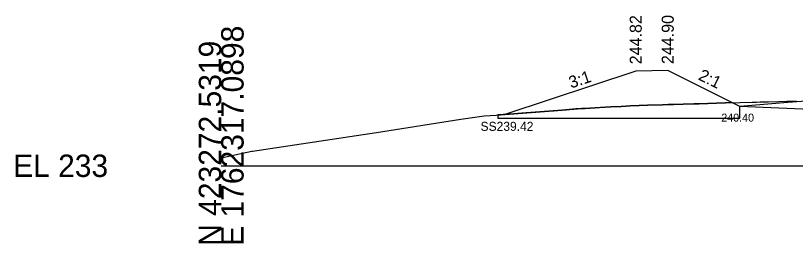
# Model space of a CAD drawing. Extents: x -26 to 3203, y -11010 to 4024.
# Drawn here: x -25.7 to 71.8, y 1490.3 to 1518.7 of the extents above; entities that cross this region are included whole.
import ezdxf

# ---------------------------------------------------------------- set-up
doc = ezdxf.new("R2010")
doc.units = 0
for name, color, linetype in [('Default', 7, 'Continuous'), ('Exist Cross Section Cell', 7, 'Continuous'), ('Exist XS Ground Line', 7, 'Continuous'), ('Prop CMT Slope Grass', 7, 'Continuous'), ('Prop CMT Subgrade Earthwork', 7, 'Continuous'), ('Prop CMT Undercut', 7, 'Continuous'), ('Prop CMT Undercut Boundary', 7, 'Continuous'), ('Prop XS Hydro Elevations', 7, 'Continuous'), ('Prop XS Side Slope Text', 7, 'Continuous'), ('Prop XS SS Elevation Text', 7, 'Continuous'), ('Scratch_Level_0', 7, 'Continuous')]:
    doc.layers.add(name, color=color, linetype=linetype)

msp = doc.modelspace()

# ---------------------------------------------------------------- linework, layer by layer
at = {"layer": 'Exist Cross Section Cell'}
msp.add_line((0, 1500), (100, 1500), dxfattribs=at)
at = {"layer": 'Exist XS Ground Line'}
msp.add_lwpolyline([(0, 1501.007), (3.245, 1501.693), (3.814, 1501.81), (3.917, 1501.827), (16.92, 1503.777), (19.387, 1504.149), (29.925, 1505.822), (32.864, 1506.212), (32.872, 1506.25), (34.364, 1506.327), (42.596, 1506.947), (45.013, 1507.156), (45.295, 1507.16), (45.468, 1507.167), (46.715, 1507.236), (47.263, 1507.263), (48.709, 1507.339), (49.975, 1507.402), (50.616, 1507.436), (51.09, 1507.463), (52.218, 1507.52), (52.239, 1507.521), (53.251, 1507.56), (55.147, 1507.621), (55.839, 1507.64), (56.531, 1507.661), (57.745, 1507.697), (59.064, 1507.73), (59.416, 1507.74), (59.737, 1507.749), (62.971, 1507.844), (62.989, 1507.845), (63.005, 1507.845), (64.862, 1507.892), (66.348, 1507.938), (66.597, 1507.945), (66.902, 1507.953), (67.349, 1507.97), (67.464, 1507.974), (67.569, 1507.978), (67.628, 1507.98), (68.359, 1507.998), (69.673, 1508.031), (70.697, 1508.055), (71.89, 1508.081)], dxfattribs=at)
msp.add_lwpolyline([(0, 1501.007), (3.245, 1501.693), (3.814, 1501.81), (3.917, 1501.827), (16.92, 1503.777), (19.387, 1504.149), (29.925, 1505.822), (32.864, 1506.212), (32.872, 1506.25), (34.364, 1506.327), (42.596, 1506.947), (45.013, 1507.156), (45.295, 1507.16), (45.468, 1507.167), (46.715, 1507.236), (47.263, 1507.263), (48.709, 1507.339), (49.975, 1507.402), (50.616, 1507.436), (51.09, 1507.463), (52.218, 1507.52), (52.239, 1507.521), (53.251, 1507.56), (55.147, 1507.621), (55.839, 1507.64), (56.531, 1507.661), (57.745, 1507.697), (59.064, 1507.73), (59.416, 1507.74), (59.737, 1507.749), (62.971, 1507.844), (62.989, 1507.845), (63.005, 1507.845), (64.862, 1507.892), (66.348, 1507.938), (66.597, 1507.945), (66.902, 1507.953), (67.349, 1507.97), (67.464, 1507.974), (67.569, 1507.978), (67.628, 1507.98), (68.359, 1507.998), (69.673, 1508.031), (70.697, 1508.055), (71.89, 1508.081)], dxfattribs=at)
msp.add_lwpolyline([(0, 1501.007), (3.245, 1501.693), (3.814, 1501.81), (3.917, 1501.827), (16.92, 1503.777), (19.387, 1504.149), (29.925, 1505.822), (32.864, 1506.212), (32.872, 1506.25), (34.364, 1506.327), (42.596, 1506.947), (45.013, 1507.156), (45.295, 1507.16), (45.468, 1507.167), (46.715, 1507.236), (47.263, 1507.263), (48.709, 1507.339), (49.975, 1507.402), (50.616, 1507.436), (51.09, 1507.463), (52.218, 1507.52), (52.239, 1507.521), (53.251, 1507.56), (55.147, 1507.621), (55.839, 1507.64), (56.531, 1507.661), (57.745, 1507.697), (59.064, 1507.73), (59.416, 1507.74), (59.737, 1507.749), (62.971, 1507.844), (62.989, 1507.845), (63.005, 1507.845), (64.862, 1507.892), (66.348, 1507.938), (66.597, 1507.945), (66.902, 1507.953), (67.349, 1507.97), (67.464, 1507.974), (67.569, 1507.978), (67.628, 1507.98), (68.359, 1507.998), (69.673, 1508.031), (70.697, 1508.055), (71.89, 1508.081)], dxfattribs=at)
msp.add_lwpolyline([(0, 1501.007), (3.245, 1501.693), (3.814, 1501.81), (3.917, 1501.827), (16.92, 1503.777), (19.387, 1504.149), (29.925, 1505.822), (32.864, 1506.212), (32.872, 1506.25), (34.364, 1506.327), (42.596, 1506.947), (45.013, 1507.156), (45.295, 1507.16), (45.468, 1507.167), (46.715, 1507.236), (47.263, 1507.263), (48.709, 1507.339), (49.975, 1507.402), (50.616, 1507.436), (51.09, 1507.463), (52.218, 1507.52), (52.239, 1507.521), (53.251, 1507.56), (55.147, 1507.621), (55.839, 1507.64), (56.531, 1507.661), (57.745, 1507.697), (59.064, 1507.73), (59.416, 1507.74), (59.737, 1507.749), (62.971, 1507.844), (62.989, 1507.845), (63.005, 1507.845), (64.862, 1507.892), (66.348, 1507.938), (66.597, 1507.945), (66.902, 1507.953), (67.349, 1507.97), (67.464, 1507.974), (67.569, 1507.978), (67.628, 1507.98), (68.359, 1507.998), (69.673, 1508.031), (70.697, 1508.055), (71.89, 1508.081)], dxfattribs=at)
msp.add_lwpolyline([(0, 1501.007), (3.245, 1501.693), (3.814, 1501.81), (3.917, 1501.827), (16.92, 1503.777), (19.387, 1504.149), (29.925, 1505.822), (32.864, 1506.212), (32.872, 1506.25), (34.364, 1506.327), (42.596, 1506.947), (45.013, 1507.156), (45.295, 1507.16), (45.468, 1507.167), (46.715, 1507.236), (47.263, 1507.263), (48.709, 1507.339), (49.975, 1507.402), (50.616, 1507.436), (51.09, 1507.463), (52.218, 1507.52), (52.239, 1507.521), (53.251, 1507.56), (55.147, 1507.621), (55.839, 1507.64), (56.531, 1507.661), (57.745, 1507.697), (59.064, 1507.73), (59.416, 1507.74), (59.737, 1507.749), (62.971, 1507.844), (62.989, 1507.845), (63.005, 1507.845), (64.862, 1507.892), (66.348, 1507.938), (66.597, 1507.945), (66.902, 1507.953), (67.349, 1507.97), (67.464, 1507.974), (67.569, 1507.978), (67.628, 1507.98), (68.359, 1507.998), (69.673, 1508.031), (70.697, 1508.055), (71.89, 1508.081)], dxfattribs=at)
at = {"layer": 'Prop CMT Slope Grass'}
msp.add_lwpolyline([(74.8, 1508.204), (70.8, 1507.884), (64.8, 1507.404), (55.8, 1511.904), (51.8, 1511.824), (35.586, 1506.419)], dxfattribs=at)
at = {"layer": 'Prop CMT Subgrade Earthwork'}
msp.add_lwpolyline([(73.61, 1507.013), (64.8, 1507.404)], dxfattribs=at)
at = {"layer": 'Prop CMT Undercut'}
msp.add_lwpolyline([(36.553, 1506.492), (34.586, 1506.344), (34.586, 1505.937), (36.553, 1505.937), (64.8, 1505.937), (64.8, 1507.404), (63.874, 1507.867), (62.971, 1507.844), (59.737, 1507.749), (59.064, 1507.73), (57.745, 1507.697), (56.531, 1507.661), (55.839, 1507.64), (55.147, 1507.621), (53.251, 1507.56), (52.218, 1507.52), (51.09, 1507.463), (50.616, 1507.436), (49.975, 1507.402), (48.709, 1507.339), (46.715, 1507.236), (45.468, 1507.167), (45.295, 1507.16), (45.013, 1507.156), (44.326, 1507.097), (42.596, 1506.947), (37.55, 1506.567), (36.553, 1506.492)], dxfattribs=at)
at = {"layer": 'Prop CMT Undercut Boundary'}
msp.add_lwpolyline([(36.553, 1506.492), (34.586, 1506.344), (34.586, 1505.937), (36.553, 1505.937), (64.8, 1505.937), (64.8, 1507.404), (63.874, 1507.867), (62.971, 1507.844), (59.737, 1507.749), (59.064, 1507.73), (57.745, 1507.697), (56.531, 1507.661), (55.839, 1507.64), (55.147, 1507.621), (53.251, 1507.56), (52.218, 1507.52), (51.09, 1507.463), (50.616, 1507.436), (49.975, 1507.402), (48.709, 1507.339), (46.715, 1507.236), (45.468, 1507.167), (45.295, 1507.16), (45.013, 1507.156), (44.326, 1507.097), (42.596, 1506.947), (37.55, 1506.567), (36.553, 1506.492)], dxfattribs=at)

# ---------------------------------------------------------------- texts
at = {"layer": 'Default'}
msp.add_text('-', height=0.0001, dxfattribs=at).set_placement((0, 1500))
msp.add_text('-', height=0.0001, dxfattribs=at).set_placement((0, 1500))
at = {"layer": 'Exist Cross Section Cell'}
for s, p in [('E 1762317.0898', (2.8, 1490)), ('N 423272.5319', (0, 1490))]:
    msp.add_text(s, height=2.8, rotation=90, dxfattribs=at).set_placement(p)
msp.add_text('EL 233', height=2.8, dxfattribs=at).set_placement((-26, 1498.6))
at = {"layer": 'Prop XS Hydro Elevations'}
for s, p in [('244.82', (52.55, 1512.664)), ('244.90', (56.55, 1512.686))]:
    msp.add_text(s, height=1.5, rotation=90, dxfattribs=at).set_placement(p)
at = {"layer": 'Prop XS Side Slope Text'}
for s, rotation, p in [('3:1', 18.43493, (43.721, 1509.636)), ('2:1', 334.09695, (59.51, 1510.796))]:
    msp.add_text(s, height=1.5, rotation=rotation, dxfattribs=at).set_placement(p)
at = {"layer": 'Prop XS SS Elevation Text'}
for s, height, p in [('240.40', 1.0001, (62.491, 1505.507)), ('SS239.42', 1.125, (32.408, 1504.357))]:
    msp.add_text(s, height=height, dxfattribs=at).set_placement(p)
at = {"layer": 'Scratch_Level_0'}
for s, p in [('LT_Berm_Top out', (51.658, 1511.814)), ('LT_Berm_Top in', (55.674, 1511.894)), ('LT_GS_OS_CTL', (70.694, 1507.874)), ('LT_Ditch_Bot', (64.695, 1507.394)), ('Exterior Boundary', (35.427, 1506.409)), ('LT_Slope_Fill', (35.492, 1506.409))]:
    msp.add_text(s, height=0.02, dxfattribs=at).set_placement(p)

doc.saveas('drawing.dxf')
